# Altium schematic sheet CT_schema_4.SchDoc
size 289 x 230 mm
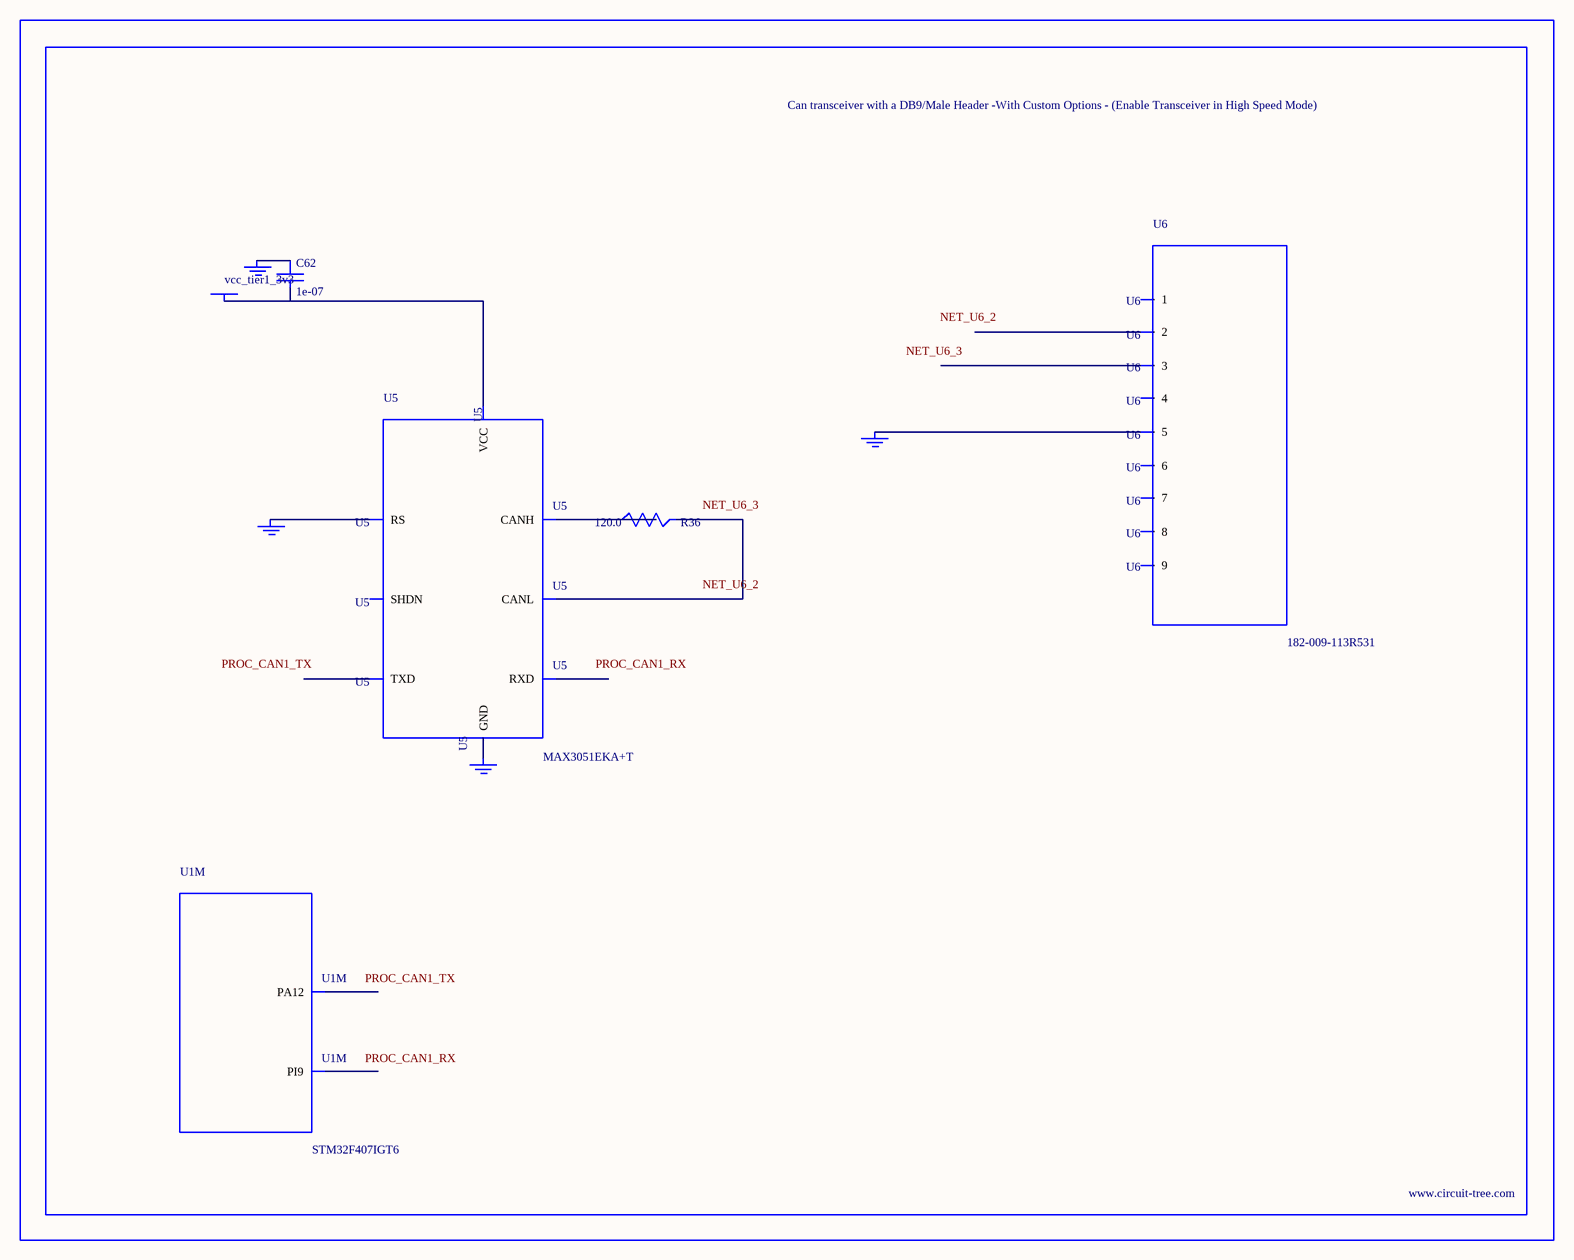
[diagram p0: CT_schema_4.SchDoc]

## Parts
BORDER3  (no value)
C62  1e-07  [C0402]
GND_INSTANCE_3_0  (no value)
GND_INSTANCE_3_1  (no value)
GND_INSTANCE_3_2  (no value)
GND_INSTANCE_3_3  (no value)
POWER_INSTANCE_3_0  vcc_tier1_3v3
R36  120.0  [R0603]
U1  STM32F407IGT6  [LQFP176]  (part M of 14)
U5  MAX3051EKA+T  [SOT-23-8]
U6  182-009-113R531  [182-009-MALE]

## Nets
NetC62_1: C62.1 GND_INSTANCE_3_0.0(GND)
NetC62_2: C62.2 POWER_INSTANCE_3_0.0(PWR) U5.3(VCC)
NetGND_INSTANCE_3_1_0: GND_INSTANCE_3_1.0(GND) U5.8(RS)
NetGND_INSTANCE_3_2_0: GND_INSTANCE_3_2.0(GND) U5.2(GND)
NetGND_INSTANCE_3_3_0: GND_INSTANCE_3_3.0(GND) U6.5
NetR36_1: R36.1 U5.7(CANH)
NetR36_2: R36.2 U5.6(CANL)

Not connected (* = marked no-connect by the designer): U1 11(PI9) 123(PA12); U5 1(TXD) 4(RXD) 5(SHDN); U6 1 2 3 4 6 7 8 9

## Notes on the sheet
- Labels drawn without touching a wire or pin: NET_U6_2, NET_U6_3, PROC_CAN1_RX, PROC_CAN1_TX

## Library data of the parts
BORDER3 = BORDER_PAGE3
C62 = C0402C104K3RACTU
GND_INSTANCE_3_0-GND_INSTANCE_3_3 = GND
POWER_INSTANCE_3_0 = PWR
R36 = RC0603JR-07120RL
